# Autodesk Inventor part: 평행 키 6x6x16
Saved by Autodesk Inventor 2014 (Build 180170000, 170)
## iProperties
Created: 2026-04
Part Number: 평행 키 6x6x16
Material: 강철, 연강
Document SubType Name: Modeling
Designer: dg
Density: 7.86 g/cm^3
Appearance: 강철
Mass: 4.11521 g
Surface Area: 3.91024 cm^2
Volume: 0.523564 cm^3
Author: jhkim
Description: 키 및 해당 키홈
Creation Date: 2026-03-27
Sending System: Autodesk Inventor 2026
Preprocessor: ST-DEVELOPER v20.1
Author: dg
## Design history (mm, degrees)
node "평행 키 6x6x161"
body "Solid1"
node "기준1"
